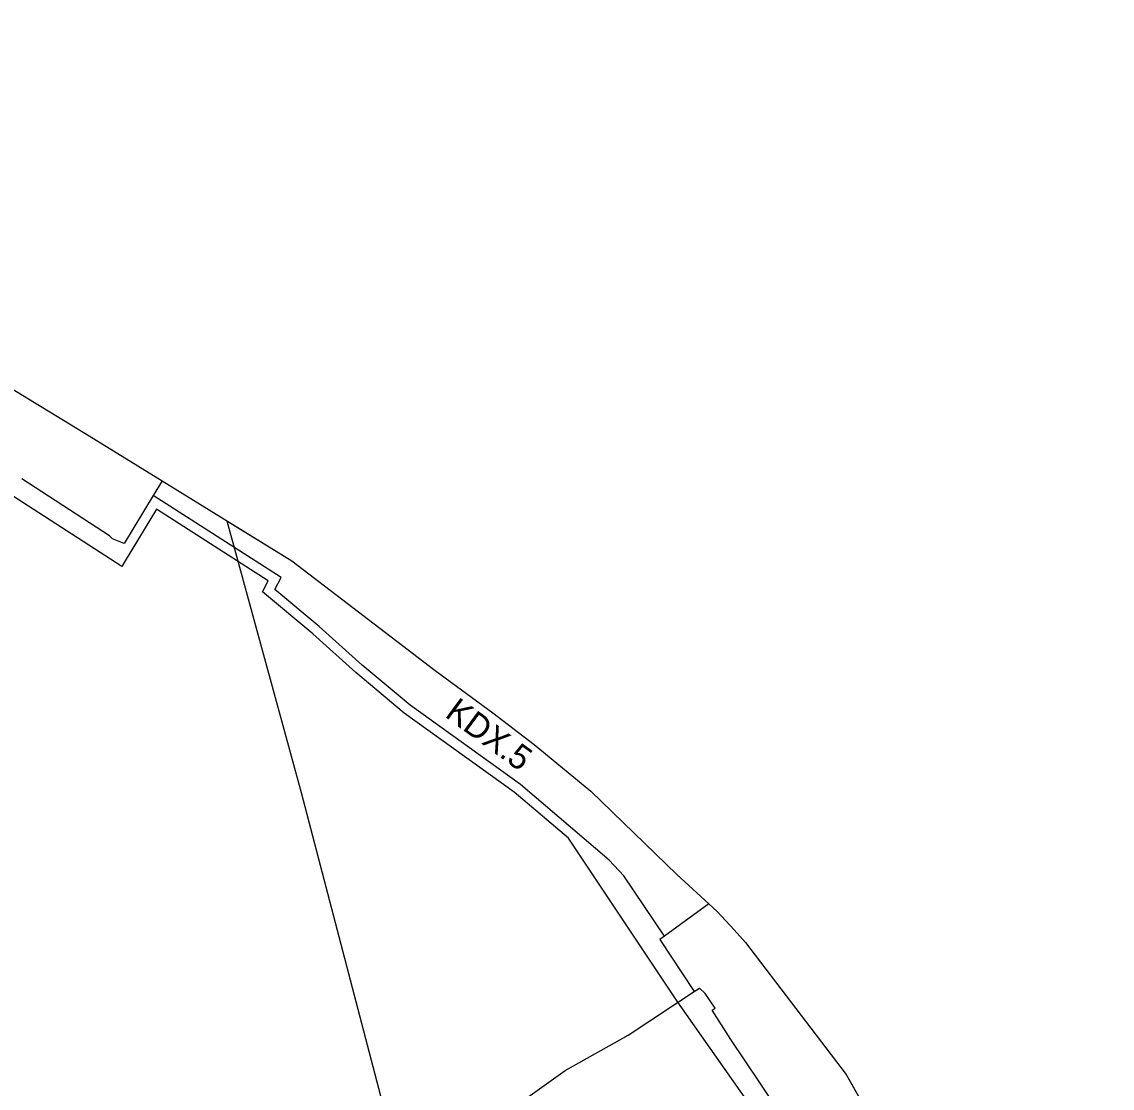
# Model space of a CAD drawing. Extents: x 7418991 to 7423142, y 5547704 to 5549547.
# Drawn here: x 7420464.2 to 7420686.6, y 5548281.5 to 5548499.1 of the extents above; entities that cross this region are included whole.
import ezdxf

# ---------------------------------------------------------------- set-up
doc = ezdxf.new("R2010")
doc.units = 0
for name, color, linetype in [('LIN_Linia Zabudowy Nieprzekraczalna', 7, 'Continuous'), ('LIN_linie_rozgraniczajace', 7, 'Continuous'), ('TRS_strefa ograniczen tunelu', 7, 'Continuous'), ('TXT_Oznaczenia_przeznaczen', 7, 'Continuous')]:
    doc.layers.add(name, color=color, linetype=linetype)

msp = doc.modelspace()

# ---------------------------------------------------------------- linework, layer by layer
at = {"layer": 'LIN_Linia Zabudowy Nieprzekraczalna'}
msp.add_lwpolyline([(7420617.3, 5548271.58), (7420598.03, 5548299.02), (7420575.67, 5548332.48), (7420564.64, 5548341.88), (7420542.17, 5548358.04), (7420532.32, 5548366.31), (7420523.5, 5548374.21), (7420513.23, 5548382.74), (7420514.45, 5548384.99), (7420491.63, 5548399.65), (7420485.03, 5548388.75), (7420485.03, 5548388.75), (7420484.55, 5548387.96), (7420462.03, 5548402.46)], dxfattribs=at)
at = {"layer": 'LIN_linie_rozgraniczajace'}
for points in [[(7420438.43, 5548499.09), (7420436.57, 5548471.43), (7420436.07, 5548464.08), (7420434.35, 5548438.55), (7420461.53, 5548424.61), (7420477.91, 5548414.57), (7420492.78, 5548405.41), (7420519.26, 5548389.1), (7420548.5, 5548366.71), (7420560.25, 5548358.05), (7420568.7, 5548351.61), (7420580.26, 5548342.08), (7420597.79, 5548325.09), (7420604.35, 5548319.1), (7420606.03, 5548317.56), (7420609.48, 5548313.8), (7420611.83, 5548311.24), (7420632.33, 5548284.25), (7420680.09, 5548200.38), (7420703.55, 5548157.78)], [(7420482.08, 5548394.21), (7420479.32, 5548395.93), (7420464.16, 5548405.84)], [(7420492.78, 5548405.41), (7420490.98, 5548402.44), (7420485.05, 5548392.65), (7420482.66, 5548393.59), (7420482.08, 5548394.21)], [(7420515.77, 5548383.23), (7420517.1, 5548385.67), (7420490.98, 5548402.44)], [(7420595.28, 5548312.51), (7420587, 5548324.84), (7420583.98, 5548328.03), (7420565.87, 5548343.46), (7420543.4, 5548359.62), (7420533.63, 5548367.82), (7420524.81, 5548375.72), (7420515.77, 5548383.23)], [(7420604.35, 5548319.1), (7420595.28, 5548312.51), (7420594.3, 5548311.79), (7420601.36, 5548301.23)], [(7420503.35, 5548214.79), (7420505.05, 5548218.68), (7420507.4, 5548223.12), (7420509.27, 5548226.37), (7420511.6, 5548229.63), (7420515.67, 5548234.43), (7420520.3, 5548238.47), (7420536.05, 5548247.72), (7420540.34, 5548251.9), (7420546.51, 5548258.56), (7420560.71, 5548274.89), (7420575.02, 5548285.1), (7420587.86, 5548292.27), (7420601.36, 5548301.23), (7420602.39, 5548301.92)], [(7420698.13, 5548154.14), (7420684.48, 5548176.24), (7420671.11, 5548198.8), (7420657.11, 5548221.03), (7420648.92, 5548232.68), (7420641.55, 5548243.41), (7420630.32, 5548259.67), (7420620.24, 5548274.37), (7420614.65, 5548282.71), (7420608.78, 5548291.44), (7420605.02, 5548297.38), (7420605.58, 5548297.78), (7420603.55, 5548300.79), (7420602.39, 5548301.92)]]:
    msp.add_lwpolyline(points, dxfattribs=at)
at = {"layer": 'TRS_strefa ograniczen tunelu'}
for points in [[(7420505.97, 5548397.28), (7420521.12, 5548341.79), (7420539.66, 5548271.1), (7420555.19, 5548204.71), (7420568.21, 5548140.79), (7420587.66, 5548025.67), (7420594.04, 5547976.4), (7420597.15, 5547951.42), (7420609.27, 5547815.84), (7420612.79, 5547774.96)], [(7420505.97, 5548397.28), (7420519.26, 5548389.1), (7420548.5, 5548366.71), (7420560.25, 5548358.05), (7420568.7, 5548351.61), (7420580.26, 5548342.08), (7420597.79, 5548325.09), (7420604.35, 5548319.1), (7420606.03, 5548317.56), (7420609.48, 5548313.8), (7420611.83, 5548311.24), (7420632.33, 5548284.25), (7420639.17, 5548272.24)]]:
    msp.add_lwpolyline(points, dxfattribs=at)

# ---------------------------------------------------------------- texts
at = {"layer": 'TXT_Oznaczenia_przeznaczen'}
msp.add_text('KDX.5', height=5, rotation=323.7066, dxfattribs=at).set_placement((7420550.26, 5548357.41))

doc.saveas('drawing.dxf')
